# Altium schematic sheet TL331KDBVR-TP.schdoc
size 127 x 101 mm
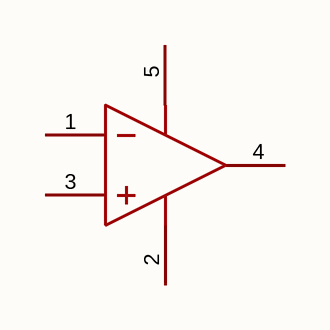
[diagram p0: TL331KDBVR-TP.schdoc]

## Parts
U?  tl331kdbvr-tp  [SOT-23-5_L2.9-W1.6-P0.95-LS2.8-BR]  (value not drawn)

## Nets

Not connected (* = marked no-connect by the designer): U? 1(IN-) 2(GND) 3(IN+) 4(OUT) 5(VCC)

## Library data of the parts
U? = tl331kdbvr-tp: 比较器数:单路;输入失调电压(Vos):2mV;输入偏置电流(Ib):250nA;; Manufacturer: TECH PUBLIC(台舟); AddInBom: yes; ModelId: 7ba65df16e7b4570af156e925f9c37fe; ModelTransform: 114.173,114.173,0,90,0,0,0,0,0; Number of Channels: 单路; Vos - Input Offset Voltage: 2mV; Ib - Input Bias Current: 250nA; Propagation Delay Time: 300ns; Output Mode: MOS；CMOS；ECL；DTL；TTL; Quiescent Current: 400uA; Maximum Power Supply Range (Vdd-Vss): 36V; Single Supply: 2V~36V; Dual Supply: -18V~-1V；1V~18V; Input Offset Current(Ios): 50nA; Response Time (tr): 1.3us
